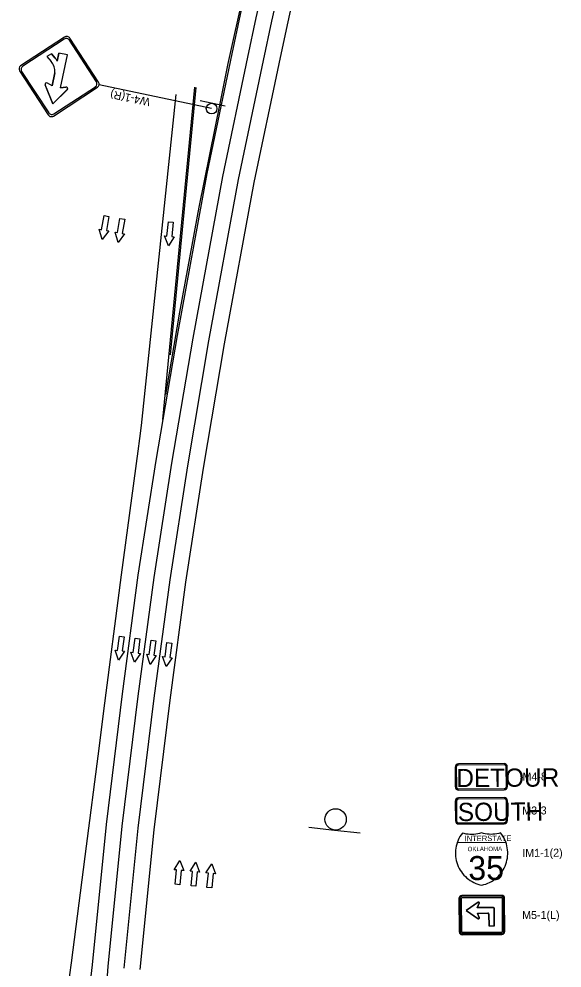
# Model space of a CAD drawing. Extents: x 2135767 to 2151731, y 141839 to 175894.
# Drawn here: x 2150734 to 2151141, y 146901 to 147612 of the extents above; entities that cross this region are included whole.
import ezdxf

# ---------------------------------------------------------------- set-up
doc = ezdxf.new("R2010")
doc.units = 0
for name, color, linetype in [('PR_Dimensions_Phase1', 7, 'Continuous'), ('PR_Phasing_Detour_1', 7, 'Continuous'), ('PR_Phasing_Traffic_Control_Devices_1', 7, 'Continuous'), ('PR_Phasing_Traffic_Striping_Dashed_Phase_1', 7, 'Continuous'), ('PR_Phasing_Traffic_Striping_White_Phase_1', 7, 'Continuous'), ('PR_Phasing_Traffic_Striping_Yellow_Phase_1', 7, 'Continuous'), ('Pr_Traffic_Arrows_Phase_1', 7, 'Continuous'), ('PR_Traffic_Striping_Dashed', 7, 'Continuous'), ('PR_Traffic_Striping_White_Temp', 7, 'Continuous'), ('PR_Txt_Phase_1', 7, 'Continuous')]:
    doc.layers.add(name, color=color, linetype=linetype)

msp = doc.modelspace()

# ---------------------------------------------------------------- linework, layer by layer
at = {"layer": 'PR_Dimensions_Phase1'}
msp.add_line((2150878.51, 147545.05), (2150794.07, 147562.78), dxfattribs=at)
at = {"layer": 'PR_Phasing_Detour_1'}
for p, q in [((2151097.87, 147054.18), (2151063.68, 147053.97)), ((2151097.87, 147053.37), (2151063.69, 147053.15)), ((2151061.25, 147051.51), (2151061.34, 147036.86)), ((2151062.07, 147051.52), (2151062.16, 147036.86)), ((2151099.6, 147037.1), (2151099.51, 147051.75)), ((2151100.42, 147037.1), (2151100.33, 147051.75)), ((2151063.8, 147035.25), (2151097.98, 147035.46)), ((2151063.8, 147034.43), (2151097.99, 147034.64)), ((2151061.34, 147026.06), (2151061.43, 147011.4)), ((2151062.15, 147026.06), (2151062.24, 147011.41)), ((2151097.95, 147028.72), (2151063.76, 147028.51)), ((2151097.96, 147027.91), (2151063.77, 147027.7)), ((2151099.69, 147011.64), (2151099.6, 147026.29)), ((2151100.5, 147011.65), (2151100.41, 147026.3)), ((2151063.88, 147009.79), (2151098.07, 147010)), ((2150951.47, 147006.59), (2150970.65, 147004.45)), ((2150970.65, 147004.45), (2150989.84, 147002.31)), ((2151063.89, 147008.98), (2151098.07, 147009.19)), ((2151062.41, 146995.04), (2151099.6, 146995.28)), ((2151064.09, 146953.09), (2151064.24, 146928.12)), ((2151064.7, 146953.1), (2151064.85, 146928.12)), ((2151064.7, 146953.1), (2151064.85, 146928.12)), ((2151065.71, 146953.1), (2151065.87, 146928.13)), ((2151065.87, 146928.13), (2151065.71, 146953.1)), ((2151096.1, 146955.46), (2151066.24, 146955.27)), ((2151096.1, 146954.85), (2151066.24, 146954.66)), ((2151096.1, 146954.85), (2151066.24, 146954.66)), ((2151096.11, 146953.83), (2151066.25, 146953.64)), ((2151066.25, 146953.64), (2151096.11, 146953.83)), ((2151096.8, 146928.32), (2151096.65, 146953.29)), ((2151096.65, 146953.29), (2151096.8, 146928.32)), ((2151097.82, 146928.33), (2151097.66, 146953.3)), ((2151097.82, 146928.33), (2151097.66, 146953.3)), ((2151098.43, 146928.33), (2151098.27, 146953.3)), ((2151078.49, 146950.37), (2151069.51, 146944.07)), ((2151077.83, 146946.2), (2151079.19, 146949.68)), ((2151089.41, 146946.27), (2151077.83, 146946.2)), ((2151090.54, 146932.6), (2151090.46, 146945.24)), ((2151069.51, 146944.07), (2151078.57, 146937.88)), ((2151077.85, 146942.04), (2151085.62, 146942.09)), ((2151079.26, 146938.58), (2151077.85, 146942.04)), ((2151086.32, 146941.4), (2151086.38, 146932.57)), ((2151086.38, 146932.57), (2151090.54, 146932.6)), ((2151066.41, 146927.59), (2151096.27, 146927.78)), ((2151096.27, 146927.78), (2151066.41, 146927.59)), ((2151066.42, 146926.58), (2151096.27, 146926.76)), ((2151066.42, 146926.58), (2151096.27, 146926.76)), ((2151066.42, 146925.97), (2151096.28, 146926.15))]:
    msp.add_line(p, q, dxfattribs=at)
for points in [[(2151066.6, 147002.14), (2151065.68, 147000.88), (2151064.84, 146999.57), (2151064.09, 146998.2), (2151063.43, 146996.79), (2151062.86, 146995.34), (2151062.38, 146993.86), (2151062, 146992.35), (2151061.72, 146990.82), (2151061.53, 146989.27), (2151061.44, 146987.72), (2151061.46, 146986.16), (2151061.57, 146984.61), (2151061.78, 146983.07), (2151062.08, 146981.54), (2151062.49, 146980.04), (2151062.99, 146978.56), (2151063.58, 146977.12), (2151064.26, 146975.72), (2151065.03, 146974.37), (2151065.89, 146973.07), (2151066.82, 146971.83), (2151067.84, 146970.64), (2151068.92, 146969.53), (2151070.08, 146968.49), (2151071.3, 146967.52), (2151072.58, 146966.63), (2151073.91, 146965.83), (2151075.29, 146965.11), (2151076.72, 146964.48), (2151078.18, 146963.94), (2151079.67, 146963.5), (2151081.19, 146963.16), (2151082.71, 146963.52), (2151084.19, 146963.98), (2151085.65, 146964.54), (2151087.06, 146965.18), (2151088.44, 146965.92), (2151089.76, 146966.74), (2151091.03, 146967.64), (2151092.24, 146968.62), (2151093.38, 146969.68), (2151094.45, 146970.81), (2151095.45, 146972), (2151096.37, 146973.26), (2151097.21, 146974.57), (2151097.96, 146975.93), (2151098.63, 146977.34), (2151099.2, 146978.79), (2151099.68, 146980.27), (2151100.07, 146981.78), (2151100.36, 146983.31), (2151100.55, 146984.85), (2151100.64, 146986.41), (2151100.63, 146987.96), (2151100.53, 146989.52), (2151100.32, 146991.06), (2151100.02, 146992.59), (2151099.62, 146994.09), (2151099.12, 146995.57), (2151098.53, 146997.01), (2151097.85, 146998.41), (2151097.09, 146999.77), (2151096.24, 147001.07), (2151095.3, 147002.32), (2151093.9, 147001.92), (2151092.48, 147001.61), (2151091.04, 147001.38), (2151089.59, 147001.25), (2151088.13, 147001.19), (2151086.68, 147001.23), (2151085.22, 147001.35), (2151083.78, 147001.56), (2151082.36, 147001.85), (2151080.95, 147002.23), (2151079.55, 147001.83), (2151078.12, 147001.52), (2151076.68, 147001.3), (2151075.23, 147001.16), (2151073.78, 147001.1), (2151072.32, 147001.14), (2151070.87, 147001.26), (2151069.43, 147001.47), (2151068, 147001.76), (2151066.6, 147002.14)], [(2151078.72, 146950.46), (2151069.74, 146944.17)], [(2151089.64, 146946.37), (2151078.05, 146946.3), (2151079.42, 146949.78)], [(2151086.55, 146941.49), (2151086.6, 146932.67), (2151090.77, 146932.69), (2151090.69, 146945.34)], [(2151069.74, 146944.17), (2151078.8, 146937.98)], [(2151079.49, 146938.68), (2151078.08, 146942.14), (2151085.85, 146942.18)]]:
    msp.add_lwpolyline(points, dxfattribs=at)
msp.add_circle((2150971.54, 147012.4), 8, dxfattribs=at)
for centre, radius, start, end in [((2151063.7, 147051.53), 2.44, 90.35558, 180.35558), ((2151063.7, 147051.53), 1.63, 90.35558, 180.35558), ((2151097.88, 147051.74), 2.44, 0.35558, 90.35558), ((2151097.88, 147051.74), 1.63, 0.35558, 90.35558), ((2151063.79, 147036.87), 2.44, 180.35558, 270.35558), ((2151063.79, 147036.87), 1.63, 180.35558, 270.35558), ((2151097.97, 147037.09), 1.63, 270.35558, 0.35558), ((2151097.97, 147037.09), 2.44, 270.35558, 0.35558), ((2151063.78, 147026.07), 2.44, 90.35558, 180.35558), ((2151063.78, 147026.07), 1.63, 90.35558, 180.35558), ((2151097.97, 147026.28), 2.44, 0.35558, 90.35558), ((2151097.97, 147026.28), 1.63, 0.35558, 90.35558), ((2151063.87, 147011.42), 2.44, 180.35558, 270.35558), ((2151063.87, 147011.42), 1.63, 180.35558, 270.35558), ((2151098.06, 147011.63), 2.44, 270.35558, 0.35558), ((2151098.06, 147011.63), 1.63, 270.35558, 0.35558), ((2151066.25, 146953.11), 2.16, 90.35558, 180.35558), ((2151066.25, 146953.11), 1.55, 90.35558, 180.35558), ((2151066.25, 146953.11), 1.55, 90.35558, 180.35558), ((2151066.25, 146953.11), 0.537, 90.35558, 180.35558), ((2151066.25, 146953.11), 0.537, 90.35558, 180.35558), ((2151096.11, 146953.29), 2.16, 0.35558, 90.35558), ((2151096.11, 146953.29), 1.55, 0.35558, 90.35558), ((2151096.11, 146953.29), 1.55, 0.35558, 90.35558), ((2151096.11, 146953.29), 0.537, 0.35558, 90.35558), ((2151096.11, 146953.29), 0.537, 0.35558, 90.35558), ((2151078.5, 146949.68), 0.694, 0.35558, 90.35558), ((2151078.73, 146949.77), 0.694, 0.35558, 90.35558), ((2151089.42, 146945.23), 1.04, 0.35558, 90.35558), ((2151089.65, 146945.33), 1.04, 0.35558, 90.35558), ((2151078.57, 146938.58), 0.694, 270.35558, 0.35558), ((2151078.8, 146938.67), 0.694, 270.35558, 0.35558), ((2151085.63, 146941.39), 0.694, 0.35558, 90.35558), ((2151085.86, 146941.49), 0.694, 0.35558, 90.35558), ((2151066.41, 146928.13), 2.16, 180.35558, 270.35558), ((2151066.41, 146928.13), 1.55, 180.35558, 270.35558), ((2151066.41, 146928.13), 1.55, 180.35558, 270.35558), ((2151066.41, 146928.13), 0.537, 180.35558, 270.35558), ((2151066.41, 146928.13), 0.537, 180.35558, 270.35558), ((2151096.26, 146928.32), 1.55, 270.35558, 0.35558), ((2151096.27, 146928.32), 1.55, 270.35558, 0.35558), ((2151096.26, 146928.32), 0.537, 270.35558, 0.35558), ((2151096.27, 146928.32), 0.537, 270.35558, 0.35558), ((2151096.26, 146928.32), 2.16, 270.35558, 0.35558)]:
    msp.add_arc(centre, radius, start, end, dxfattribs=at)
at = {"layer": 'PR_Phasing_Traffic_Control_Devices_1'}
for p, q in [((2150768.25, 147598.68), (2150735.28, 147577.15)), ((2150767.93, 147597.12), (2150736.84, 147576.82)), ((2150792.12, 147565.22), (2150771.82, 147596.3)), ((2150793.67, 147564.89), (2150772.15, 147597.86)), ((2150758.35, 147586.17), (2150755.03, 147584)), ((2150758.35, 147586.17), (2150755.03, 147584)), ((2150761.17, 147582.9), (2150758.35, 147586.17)), ((2150762.74, 147580.66), (2150763.98, 147586.6)), ((2150763.98, 147586.6), (2150762.74, 147580.66)), ((2150770.41, 147585.25), (2150763.98, 147586.6)), ((2150770.41, 147585.25), (2150763.98, 147586.6)), ((2150765.25, 147560.68), (2150770.41, 147585.25)), ((2150765.25, 147560.68), (2150770.41, 147585.25)), ((2150755.03, 147584), (2150758.15, 147580.37)), ((2150734.47, 147573.26), (2150755.99, 147540.29)), ((2150736.02, 147572.93), (2150756.32, 147541.85)), ((2150758.83, 147562.03), (2150760.91, 147571.94)), ((2150760.91, 147571.94), (2150758.83, 147562.03)), ((2150758.83, 147562.03), (2150755.4, 147564.12)), ((2150758.83, 147562.03), (2150755.4, 147564.12)), ((2150759.34, 147548.51), (2150753.69, 147562.91)), ((2150759.34, 147548.51), (2150770.3, 147559.42)), ((2150759.89, 147539.47), (2150792.86, 147561)), ((2150760.21, 147541.03), (2150791.3, 147561.33)), ((2150765.25, 147560.68), (2150769.23, 147561.22)), ((2150769.23, 147561.22), (2150765.25, 147560.68)), ((2150847.58, 147360.44), (2150866.91, 147560.89)), ((2150879.32, 147548.96), (2150869.87, 147550.93)), ((2150888.77, 147546.99), (2150879.32, 147548.96))]:
    msp.add_line(p, q, dxfattribs=at)
for points in [[(2150758.35, 147586.17), (2150761.17, 147582.9)], [(2150755.03, 147584), (2150758.15, 147580.37)], [(2150753.69, 147562.91), (2150753.77, 147562.7), (2150759.34, 147548.51)], [(2150759.34, 147548.51), (2150770.14, 147559.26), (2150770.3, 147559.42)]]:
    msp.add_lwpolyline(points, dxfattribs=at)
msp.add_circle((2150878.51, 147545.05), 4, dxfattribs=at)
for centre, radius, start, end in [((2150769.46, 147594.77), 2.81, 33.14189, 123.14189), ((2150769.79, 147596.32), 2.81, 33.14189, 123.14189), ((2150749.05, 147572.73), 11.89, 356.2046, 40.01411), ((2150749.05, 147572.73), 11.89, 356.2046, 40.01411), ((2150749.05, 147572.73), 15.82, 30.09196, 40.01411), ((2150749.05, 147572.73), 15.82, 30.09196, 40.01411), ((2150736.82, 147574.8), 2.81, 123.14189, 213.14189), ((2150738.38, 147574.47), 2.81, 123.14189, 213.14189), ((2150754.76, 147563.21), 1.11, 54.99283, 207.2585), ((2150754.76, 147563.21), 1.11, 54.99283, 195.59671), ((2150789.76, 147563.68), 2.81, 303.14189, 33.14189), ((2150791.32, 147563.35), 2.81, 303.14189, 33.14189), ((2150769.44, 147560.13), 1.11, 309.02529, 101.29095), ((2150769.44, 147560.13), 1.11, 320.68708, 101.29095), ((2150758.35, 147541.83), 2.81, 213.14189, 303.14189), ((2150758.68, 147543.38), 2.81, 213.14189, 303.14189)]:
    msp.add_arc(centre, radius, start, end, dxfattribs=at)
at = {"layer": 'PR_Phasing_Traffic_Striping_Dashed_Phase_1'}
for points in [[(2150995.74, 147969.08), (2150950.37, 147776.89), (2150940.94, 147739.03), (2150931.96, 147702.12), (2150918.66, 147644.1), (2150911.66, 147613.02), (2150905.36, 147583.63), (2150886.72, 147494.19), (2150864.4, 147373), (2150848.54, 147279.36), (2150835.18, 147193.58), (2150823.27, 147104.86), (2150811.29, 147007.23), (2150800.78, 146902.18)], [(2151007.42, 147966.34), (2150962.05, 147774.13), (2150952.59, 147736.16), (2150943.64, 147699.36), (2150930.36, 147641.44), (2150923.38, 147610.45), (2150917.1, 147581.15), (2150898.5, 147491.88), (2150876.21, 147370.91), (2150860.38, 147277.43), (2150847.06, 147191.86), (2150835.17, 147103.34), (2150823.22, 147005.9), (2150812.72, 146901.05)]]:
    msp.add_lwpolyline(points, dxfattribs=at)
msp.add_arc((2155616.86, 146446.48), 4837.59, 174.59467, 176.52543, dxfattribs=at)
at = {"layer": 'PR_Phasing_Traffic_Striping_White_Phase_1'}
msp.add_line((2150841.92, 147312.14), (2150865.91, 147560.99), dxfattribs=at)
for points in [[(2150844.08, 147330.86), (2150854.76, 147392.44), (2150859.26, 147416.88), (2150869.28, 147471.25), (2150885.09, 147550.09), (2150891.06, 147578.73), (2150902.57, 147631.82), (2150907.89, 147655.55), (2150914.5, 147684.71), (2150921.42, 147713.68), (2150927.15, 147737.32), (2150936.71, 147777.61), (2150983.08, 147972.05), (2151032.99, 148164.86), (2151036.14, 148181.71)], [(2150773.38, 146904.84), (2150783.61, 146984.51), (2150794.44, 147067.65), (2150797.76, 147093.85), (2150810.94, 147195.63), (2150823.35, 147288.25), (2150824.63, 147297.75), (2150825.94, 147307.7), (2150851.95, 147555.58)]]:
    msp.add_lwpolyline(points, dxfattribs=at)
msp.add_arc((2130411.85, 149402.07), 20514.09, 352.603044, 353.00792, dxfattribs=at)
at = {"layer": 'PR_Phasing_Traffic_Striping_Yellow_Phase_1'}
msp.add_lwpolyline([(2150973.73, 147771.38), (2150971.08, 147760.75), (2150964.25, 147733.29), (2150955.32, 147696.6), (2150942.06, 147638.78), (2150935.1, 147607.87), (2150928.84, 147578.67), (2150910.27, 147489.57), (2150888.03, 147368.82), (2150872.23, 147275.51), (2150858.93, 147190.14), (2150847.07, 147101.81), (2150835.15, 147004.57), (2150824.67, 146899.92)], dxfattribs=at)
at = {"layer": 'Pr_Traffic_Arrows_Phase_1'}
for p, q in [((2150796.03, 147454.31), (2150797.97, 147464.93)), ((2150797.97, 147464.93), (2150801.51, 147464.29)), ((2150801.51, 147464.29), (2150799.57, 147453.66)), ((2150807.84, 147452.16), (2150809.77, 147462.78)), ((2150809.77, 147462.78), (2150813.32, 147462.14)), ((2150813.32, 147462.14), (2150811.38, 147451.51)), ((2150845.05, 147449.51), (2150846.17, 147460.25)), ((2150846.17, 147460.25), (2150849.75, 147459.87)), ((2150849.75, 147459.87), (2150848.63, 147449.13)), ((2150796.51, 147446.9), (2150794.26, 147454.63)), ((2150794.26, 147454.63), (2150796.03, 147454.31)), ((2150801.34, 147453.34), (2150796.51, 147446.9)), ((2150799.57, 147453.66), (2150801.34, 147453.34)), ((2150808.32, 147444.75), (2150806.07, 147452.48)), ((2150806.07, 147452.48), (2150807.84, 147452.16)), ((2150813.15, 147451.19), (2150808.32, 147444.75)), ((2150811.38, 147451.51), (2150813.15, 147451.19)), ((2150846.09, 147442.16), (2150843.26, 147449.7)), ((2150843.26, 147449.7), (2150845.05, 147449.51)), ((2150850.42, 147448.94), (2150846.09, 147442.16)), ((2150848.63, 147449.13), (2150850.42, 147448.94)), ((2150807.89, 147139.1), (2150809.32, 147149.8)), ((2150809.32, 147149.8), (2150812.89, 147149.32)), ((2150812.89, 147149.32), (2150811.45, 147138.62)), ((2150819.78, 147137.5), (2150821.22, 147148.2)), ((2150821.22, 147148.2), (2150824.78, 147147.73)), ((2150824.78, 147147.73), (2150823.35, 147137.02)), ((2150831.67, 147135.9), (2150833.11, 147146.61)), ((2150833.11, 147146.61), (2150836.68, 147146.13)), ((2150836.68, 147146.13), (2150835.24, 147135.42)), ((2150843.57, 147134.31), (2150845, 147145.01)), ((2150845, 147145.01), (2150848.57, 147144.53)), ((2150848.57, 147144.53), (2150847.13, 147133.83)), ((2150808.71, 147131.72), (2150806.1, 147139.34)), ((2150806.1, 147139.34), (2150807.89, 147139.1)), ((2150813.24, 147138.38), (2150808.71, 147131.72)), ((2150811.45, 147138.62), (2150813.24, 147138.38)), ((2150820.6, 147130.13), (2150818, 147137.74)), ((2150818, 147137.74), (2150819.78, 147137.5)), ((2150825.13, 147136.78), (2150820.6, 147130.13)), ((2150823.35, 147137.02), (2150825.13, 147136.78)), ((2150832.5, 147128.53), (2150829.89, 147136.14)), ((2150829.89, 147136.14), (2150831.67, 147135.9)), ((2150837.02, 147135.19), (2150832.5, 147128.53)), ((2150835.24, 147135.42), (2150837.02, 147135.19)), ((2150844.39, 147126.93), (2150841.78, 147134.55)), ((2150841.78, 147134.55), (2150843.57, 147134.31)), ((2150848.92, 147133.59), (2150844.39, 147126.93)), ((2150847.13, 147133.83), (2150848.92, 147133.59)), ((2150850.42, 146974.71), (2150854.7, 146981.53)), ((2150854.7, 146981.53), (2150857.59, 146974.01)), ((2150852.21, 146974.54), (2150850.42, 146974.71)), ((2150851.16, 146963.79), (2150852.21, 146974.54)), ((2150855.79, 146974.19), (2150854.74, 146963.44)), ((2150857.59, 146974.01), (2150855.79, 146974.19)), ((2150862.36, 146973.55), (2150866.65, 146980.36)), ((2150866.65, 146980.36), (2150869.53, 146972.85)), ((2150874.31, 146972.38), (2150878.59, 146979.2)), ((2150878.59, 146979.2), (2150881.47, 146971.68)), ((2150864.15, 146973.37), (2150862.36, 146973.55)), ((2150863.1, 146962.62), (2150864.15, 146973.37)), ((2150867.74, 146973.02), (2150866.69, 146962.27)), ((2150869.53, 146972.85), (2150867.74, 146973.02)), ((2150876.1, 146972.21), (2150874.31, 146972.38)), ((2150875.05, 146961.46), (2150876.1, 146972.21)), ((2150879.68, 146971.86), (2150878.63, 146961.11)), ((2150881.47, 146971.68), (2150879.68, 146971.86)), ((2150854.74, 146963.44), (2150851.16, 146963.79)), ((2150866.69, 146962.27), (2150863.1, 146962.62)), ((2150878.63, 146961.11), (2150875.05, 146961.46))]:
    msp.add_line(p, q, dxfattribs=at)
at = {"layer": 'PR_Traffic_Striping_Dashed'}
msp.add_lwpolyline([(2150841.92, 147312.14), (2150836.69, 147281.28), (2150823.3, 147195.31), (2150811.36, 147106.39), (2150799.37, 147008.56), (2150788.84, 146903.38)], dxfattribs=at)
msp.add_arc((2155616.86, 146446.48), 4849.59, 174.59467, 175.39884, dxfattribs=at)
at = {"layer": 'PR_Traffic_Striping_White_Temp'}
msp.add_lwpolyline([(2150984.05, 147971.82), (2150938.69, 147779.65), (2150929.29, 147741.9), (2150920.28, 147704.88), (2150906.96, 147646.76), (2150899.93, 147615.6), (2150893.62, 147586.11), (2150874.95, 147496.5), (2150852.58, 147375.09), (2150841.92, 147312.14)], dxfattribs=at)

# ---------------------------------------------------------------- texts
at = {"layer": 'PR_Phasing_Detour_1'}
for s, height, p in [('DETOUR', 13.675, (2151062.11, 147036.59)), ('M4-8', 6, (2151111.73, 147041.5)), ('SOUTH', 13.675, (2151063.24, 147011.14)), ('M3-3', 6, (2151111.56, 147016.04)), ('INTERSTATE', 4.084, (2151068.36, 146996.07)), ('OKLAHOMA', 3.31, (2151070.58, 146988.57)), ('IM1-1(2)', 6, (2151111.57, 146984.3)), ('35', 17.974, (2151071.13, 146966.93)), ('M5-1(L)', 6, (2151111.47, 146937.7))]:
    msp.add_text(s, height=height, rotation=0.35558, dxfattribs=at).set_placement(p)
at = {"layer": 'PR_Txt_Phase_1'}
msp.add_text('W4-1(R)', height=6, rotation=168.14189, dxfattribs=at).set_placement((2150832.85, 147552.68))

doc.saveas('drawing.dxf')
